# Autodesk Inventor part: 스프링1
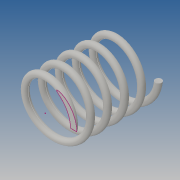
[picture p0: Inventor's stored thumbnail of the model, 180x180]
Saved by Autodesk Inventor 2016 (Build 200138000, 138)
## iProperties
Created: 2016-10
Part Number: 스프링1
Material: Generic
Document SubType Name: Modeling
Designer: Administrator
Density: 1 g/cm^3
Appearance: Default
Author: Administrator
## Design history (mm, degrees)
sketch "스케치1"
  geometry: L1 (0, 0)-(-9, 0); L2 (-9, 0)-(-9, -27); L3 (-9, -27)-(0, -27); L4 (0, -27)-(0, 0); C1 r 1 at (-9, 0)
  constraints: 8 end point, 2 parallel, 1 centre point, 1 coincident, 1 horizontal, 1 perpendicular
  dimensions: "d0" = 2 diameter of C1; "d1" = 27 distance of L1.end L2.end (derived); "d2" = 18 diameter of L2 L4
feature "코일1" sketch "스케치1" pitch "d3" = 10; turns "d5" = 5; dims "d4" = 27 (= d1), "d6" = 0, angle "d7" = 90 deg, angle "d8" = 90 deg, "d9" = 0, "d10" = 0
sketch "스케치2"
  geometry: L1 (10, 0)-(8, 0) reference; 1 further point
  constraints: 1 horizontal alignment
  node "절단 모서리 투영1"
extrude "돌출1" cut sketch "스케치2" stored distance "d11" = 10; taper "d12" = 0 deg
node "솔리드1"
